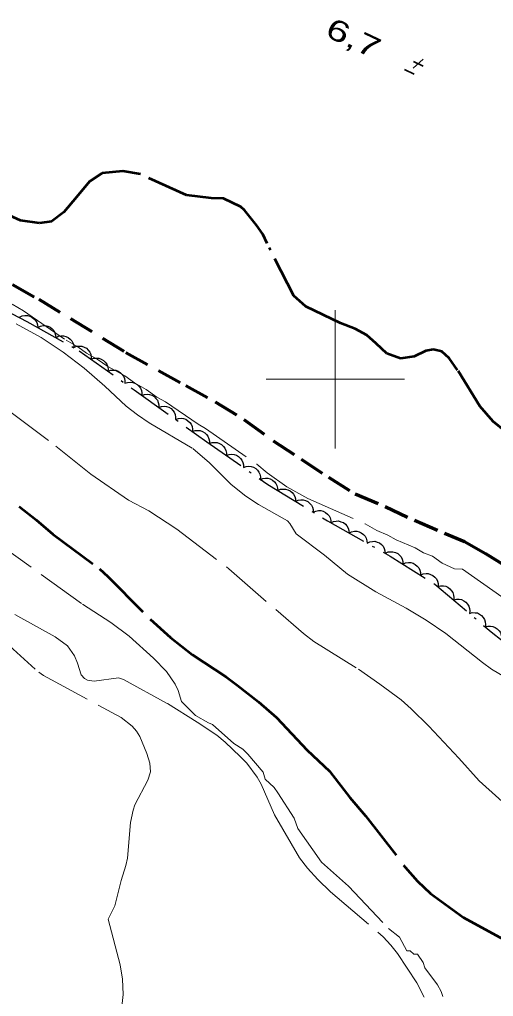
# Model space of a CAD drawing. Extents: x 355726 to 357533, y 5103782 to 5105258.
# Drawn here: x 356377.2 to 356411.4, y 5104355.4 to 5104426 of the extents above; entities that cross this region are included whole.
import ezdxf
from ezdxf.enums import TextEntityAlignment as Align

# ---------------------------------------------------------------- set-up
doc = ezdxf.new("R2010")
doc.units = 0
doc.header["$LTSCALE"] = 0.6
for name, pattern in [('DASH_DOUBLE_DOT', [9.2, 5, -1.2, 0.3, -1.2, 0.3, -1.2]), ('DOT_DASHED', [7.7, 5, -1.2, 0.3, -1.2]), ('LONG_DASHED', [7.5, 6, -1.5]), ('MEDIUM_DASHED', [4.5, 3, -1.5])]:
    doc.linetypes.add(name, pattern=pattern)
for name, color, linetype, lineweight in [('1', 7, 'LONG_DASHED', 53), ('2', 7, 'LONG_DASHED', 13), ('3', 7, 'Continuous', 140), ('4', 7, 'DASH_DOUBLE_DOT', 53), ('44', 7, 'Continuous', 25), ('61', 7, 'Continuous', 13), ('7', 7, 'MEDIUM_DASHED', 70)]:
    doc.layers.add(name, color=color, linetype=linetype, lineweight=lineweight)

msp = doc.modelspace()

# ---------------------------------------------------------------- linework, layer by layer
at = {"layer": '1'}
msp.add_lwpolyline([(356377.13, 5104390.8), (356378.36, 5104389.84), (356379.57, 5104388.8), (356382.95, 5104386.29), (356383.56, 5104385.74), (356386.6, 5104382.66), (356388.08, 5104381.32), (356389.68, 5104380.07), (356392.12, 5104378.47), (356392.91, 5104377.88), (356394.45, 5104376.68), (356395.75, 5104375.54), (356397.97, 5104373.19), (356399.57, 5104371.66), (356401.04, 5104369.76), (356402.18, 5104368.43), (356405.06, 5104364.72), (356405.94, 5104363.71), (356406.88, 5104362.82), (356409.26, 5104361.09), (356412.39, 5104359.38)], dxfattribs=at)
at = {"layer": '2'}
for points in [[(356362.95, 5104407.05), (356368.1, 5104403.34), (356373.75, 5104399.82), (356376.37, 5104397.74), (356379.79, 5104395.17), (356382.33, 5104393.13), (356385.04, 5104391.26), (356386.51, 5104390.48), (356388.54, 5104389.15), (356392.29, 5104386.3), (356397.69, 5104381.62), (356398.45, 5104381.05), (356401.68, 5104379.03), (356403.23, 5104377.96), (356404.75, 5104376.82), (356405.49, 5104376.18), (356406.75, 5104374.93), (356408.93, 5104372.61), (356410.4, 5104370.97), (356416.1, 5104365.82)], [(356376.63, 5104405.41), (356377.46, 5104404.94), (356380.54, 5104402.81), (356381.38, 5104402.34), (356382.01, 5104401.88), (356382.77, 5104401.45), (356383.56, 5104400.91)], [(356376.91, 5104403.99), (356378.74, 5104403.01), (356380.31, 5104401.95), (356381.84, 5104400.8), (356383.34, 5104399.5), (356384.87, 5104398.05), (356385.69, 5104397.42), (356386.54, 5104396.84), (356389.69, 5104394.98), (356390.9, 5104393.96), (356392.47, 5104392.38), (356393.52, 5104391.55), (356394.45, 5104390.93), (356396.53, 5104389.76), (356396.71, 5104389.57), (356397.16, 5104388.82), (356399.22, 5104387.28), (356400.88, 5104385.91), (356402.93, 5104384.63), (356405.13, 5104383.46), (356406.57, 5104382.58), (356407.98, 5104381.61), (356410.63, 5104379.51), (356411.29, 5104379.04), (356413.4, 5104377.78)], [(356383.56, 5104400.91), (356384.77, 5104400.23), (356385.48, 5104399.73), (356386.31, 5104399.26), (356387.1, 5104398.71), (356387.71, 5104398.37), (356390.08, 5104396.74), (356390.61, 5104396.44), (356394.33, 5104393.85), (356395.07, 5104393.23), (356396.5, 5104392.23), (356398.01, 5104391.38), (356402.16, 5104389.54), (356402.99, 5104389.07), (356403.79, 5104388.72), (356404.39, 5104388.38), (356405.77, 5104387.81), (356406.37, 5104387.46), (356407.02, 5104387.2), (356407.73, 5104386.7), (356408.61, 5104386.3), (356409.19, 5104386.27), (356412.04, 5104384.27)], [(356375.08, 5104388.51), (356381.72, 5104383.73), (356383.77, 5104382.41), (356385.1, 5104381.42), (356386.86, 5104379.84), (356387.8, 5104378.88), (356388.43, 5104377.95), (356388.64, 5104377.49), (356388.88, 5104376.7), (356389.9, 5104375.69), (356390.83, 5104375.15), (356391.12, 5104375.05), (356392.66, 5104373.67), (356393.31, 5104373.26), (356393.67, 5104372.9), (356394.79, 5104371.59), (356394.93, 5104371.09), (356395.58, 5104370.48), (356395.84, 5104370.11), (356397.02, 5104368.26), (356397.29, 5104367.53), (356398.99, 5104365.08), (356400.96, 5104363.36), (356403.84, 5104360.29), (356404.63, 5104359.67), (356405.16, 5104358.69), (356405.42, 5104358.69), (356405.68, 5104358.44), (356405.94, 5104358.44)], [(356376.82, 5104382.99), (356379.74, 5104381.38), (356380.64, 5104380.72), (356381.13, 5104380.01), (356381.35, 5104379.47), (356381.61, 5104378.63), (356381.86, 5104378.36), (356382.08, 5104378.24), (356382.55, 5104378.17), (356384.31, 5104378.42), (356384.68, 5104378.3), (356387.87, 5104376.55), (356390.01, 5104375.22), (356391.43, 5104374.26), (356392.04, 5104373.76), (356393.13, 5104372.72), (356393.59, 5104372.24), (356394.34, 5104371.24), (356394.64, 5104370.72), (356395.6, 5104368.51), (356397.41, 5104365.41), (356397.98, 5104364.65), (356398.73, 5104363.83), (356399.66, 5104362.94), (356403.46, 5104359.7)], [(356375.62, 5104381.44), (356378.56, 5104378.82), (356378.89, 5104378.59), (356384.51, 5104375.54), (356385.31, 5104374.93), (356385.62, 5104374.57), (356385.87, 5104374.18), (356386.37, 5104372.95), (356386.58, 5104372.24), (356386.64, 5104371.63), (356386.45, 5104371.01), (356385.5, 5104369.23), (356385.37, 5104368.84), (356385.19, 5104367.95), (356384.98, 5104365.37), (356384.86, 5104364.84), (356384.51, 5104363.76), (356384.06, 5104361.93), (356383.58, 5104360.97), (356384.43, 5104357.67), (356384.6, 5104356.63), (356384.67, 5104355.53), (356384.43, 5104353.47)], [(356403.46, 5104359.7), (356404.02, 5104359.09), (356404.5, 5104358.48), (356405.9, 5104356.36), (356406.43, 5104355.34)], [(356405.94, 5104358.44), (356406.34, 5104357.83), (356406.47, 5104357.46), (356407.38, 5104356.23), (356407.65, 5104355.74), (356407.78, 5104355.37)]]:
    msp.add_lwpolyline(points, dxfattribs=at)
at = {"layer": '3', "lineweight": 35}
for p, q in [((356406.35, 5104423.12), (356405.64, 5104422.48)), ((356405.65, 5104422.95), (356406.35, 5104422.62)), ((356404.99, 5104422.38), (356405.71, 5104422.04))]:
    msp.add_line(p, q, dxfattribs=at)
at = {"layer": '4'}
msp.add_lwpolyline([(356412.31, 5104396.23), (356411.41, 5104396.93), (356410.46, 5104398.06), (356408.84, 5104400.66), (356408.22, 5104401.51), (356407.7, 5104402), (356407.09, 5104402.15), (356406.54, 5104402.06), (356405.7, 5104401.64), (356404.72, 5104401.49), (356403.73, 5104401.86), (356402.95, 5104402.59), (356402.28, 5104403.17), (356401.44, 5104403.64), (356400.37, 5104404.04), (356397.87, 5104405.25), (356397.01, 5104406.03), (356395.06, 5104409.81), (356394.75, 5104410.49), (356394.31, 5104411.13), (356393.43, 5104412.22), (356393.17, 5104412.46), (356391.92, 5104413.07), (356391.02, 5104413.08), (356389.25, 5104413.29), (356385.91, 5104414.81), (356384.64, 5104415.03), (356383.15, 5104414.88), (356382.23, 5104414.3), (356381.28, 5104413.15), (356380.37, 5104412.08), (356379.48, 5104411.39), (356378.62, 5104411.28), (356377.23, 5104411.46), (356375.4, 5104412.29)], dxfattribs=at)
at = {"layer": '44', "linetype": 'DOT_DASHED'}
msp.add_lwpolyline([(356337.38, 5104422.65), (356344.89, 5104419.02), (356351.48, 5104415.89), (356356.51, 5104413.86), (356359.85, 5104412.37), (356363.96, 5104410.85), (356367.24, 5104409.6), (356377.7, 5104404.18), (356381.48, 5104402.05), (356385.46, 5104399.22), (356390.71, 5104395.47), (356395.13, 5104392.38), (356399.43, 5104389.76), (356403.96, 5104387.21), (356407.2, 5104385.19), (356411.38, 5104381.65), (356413.99, 5104379.58)], dxfattribs=at)
at = {"layer": '44'}
for points in [[(356377.17, 5104404.48), (356377.36, 5104404.57), (356377.56, 5104404.6), (356377.73, 5104404.61), (356377.9, 5104404.56), (356378.06, 5104404.49), (356378.21, 5104404.37), (356378.33, 5104404.25), (356378.41, 5104404.1), (356378.47, 5104403.92), (356378.48, 5104403.74)], [(356378.48, 5104403.74), (356378.67, 5104403.83), (356378.87, 5104403.87), (356379.03, 5104403.87), (356379.2, 5104403.83), (356379.37, 5104403.75), (356379.52, 5104403.63), (356379.64, 5104403.52), (356379.72, 5104403.36), (356379.77, 5104403.18), (356379.79, 5104403)], [(356379.79, 5104403), (356379.97, 5104403.1), (356380.18, 5104403.13), (356380.34, 5104403.14), (356380.51, 5104403.09), (356380.68, 5104403.02), (356380.83, 5104402.9), (356380.94, 5104402.78), (356381.02, 5104402.62), (356381.08, 5104402.45), (356381.09, 5104402.27)], [(356381.12, 5104402.31), (356381.32, 5104402.38), (356381.52, 5104402.39), (356381.68, 5104402.38), (356381.85, 5104402.32), (356382.01, 5104402.23), (356382.14, 5104402.09), (356382.24, 5104401.96), (356382.31, 5104401.8), (356382.35, 5104401.62), (356382.34, 5104401.44)], [(356382.34, 5104401.44), (356382.54, 5104401.51), (356382.74, 5104401.52), (356382.91, 5104401.51), (356383.07, 5104401.45), (356383.23, 5104401.36), (356383.36, 5104401.22), (356383.47, 5104401.09), (356383.53, 5104400.93), (356383.57, 5104400.75), (356383.56, 5104400.57)], [(356383.56, 5104400.57), (356383.76, 5104400.64), (356383.96, 5104400.65), (356384.13, 5104400.64), (356384.29, 5104400.58), (356384.45, 5104400.49), (356384.59, 5104400.35), (356384.69, 5104400.22), (356384.75, 5104400.06), (356384.79, 5104399.88), (356384.79, 5104399.7)], [(356384.79, 5104399.7), (356384.98, 5104399.77), (356385.19, 5104399.78), (356385.35, 5104399.77), (356385.51, 5104399.71), (356385.67, 5104399.62), (356385.81, 5104399.48), (356385.91, 5104399.36), (356385.98, 5104399.19), (356386.01, 5104399.01), (356386.01, 5104398.83)], [(356386.01, 5104398.83), (356386.2, 5104398.9), (356386.41, 5104398.91), (356386.57, 5104398.9), (356386.74, 5104398.84), (356386.9, 5104398.75), (356387.03, 5104398.61), (356387.13, 5104398.48), (356387.2, 5104398.32), (356387.23, 5104398.14), (356387.23, 5104397.96)], [(356387.23, 5104397.96), (356387.42, 5104398.03), (356387.63, 5104398.04), (356387.79, 5104398.03), (356387.96, 5104397.97), (356388.12, 5104397.87), (356388.25, 5104397.74), (356388.35, 5104397.61), (356388.42, 5104397.45), (356388.45, 5104397.26), (356388.45, 5104397.08)], [(356388.45, 5104397.08), (356388.65, 5104397.16), (356388.85, 5104397.17), (356389.01, 5104397.16), (356389.18, 5104397.1), (356389.34, 5104397), (356389.47, 5104396.87), (356389.57, 5104396.74), (356389.64, 5104396.57), (356389.67, 5104396.39), (356389.67, 5104396.21)], [(356389.67, 5104396.21), (356389.87, 5104396.29), (356390.07, 5104396.3), (356390.23, 5104396.29), (356390.4, 5104396.22), (356390.56, 5104396.13), (356390.69, 5104395.99), (356390.79, 5104395.87), (356390.86, 5104395.7), (356390.9, 5104395.52), (356390.89, 5104395.34)], [(356390.89, 5104395.34), (356391.09, 5104395.42), (356391.29, 5104395.43), (356391.45, 5104395.42), (356391.62, 5104395.36), (356391.78, 5104395.27), (356391.92, 5104395.13), (356392.02, 5104395.01), (356392.08, 5104394.84), (356392.12, 5104394.66), (356392.12, 5104394.48)], [(356392.12, 5104394.48), (356392.32, 5104394.56), (356392.52, 5104394.57), (356392.68, 5104394.56), (356392.85, 5104394.5), (356393.01, 5104394.41), (356393.15, 5104394.27), (356393.25, 5104394.15), (356393.31, 5104393.98), (356393.35, 5104393.8), (356393.35, 5104393.62)], [(356393.35, 5104393.62), (356393.55, 5104393.7), (356393.75, 5104393.71), (356393.91, 5104393.7), (356394.08, 5104393.64), (356394.24, 5104393.55), (356394.38, 5104393.42), (356394.48, 5104393.29), (356394.54, 5104393.13), (356394.58, 5104392.94), (356394.58, 5104392.76)], [(356394.56, 5104392.73), (356394.75, 5104392.82), (356394.95, 5104392.84), (356395.11, 5104392.84), (356395.28, 5104392.79), (356395.45, 5104392.71), (356395.59, 5104392.59), (356395.7, 5104392.47), (356395.78, 5104392.31), (356395.83, 5104392.13), (356395.84, 5104391.95)], [(356395.84, 5104391.95), (356396.03, 5104392.04), (356396.23, 5104392.06), (356396.39, 5104392.06), (356396.56, 5104392.01), (356396.73, 5104391.93), (356396.87, 5104391.8), (356396.98, 5104391.69), (356397.06, 5104391.53), (356397.11, 5104391.35), (356397.12, 5104391.17)], [(356397.12, 5104391.17), (356397.31, 5104391.25), (356397.51, 5104391.28), (356397.68, 5104391.28), (356397.84, 5104391.23), (356398.01, 5104391.15), (356398.15, 5104391.02), (356398.27, 5104390.9), (356398.34, 5104390.75), (356398.39, 5104390.57), (356398.4, 5104390.39)], [(356398.4, 5104390.39), (356398.59, 5104390.47), (356398.79, 5104390.5), (356398.96, 5104390.5), (356399.13, 5104390.45), (356399.29, 5104390.37), (356399.44, 5104390.24), (356399.55, 5104390.12), (356399.62, 5104389.97), (356399.67, 5104389.79), (356399.68, 5104389.61)], [(356399.69, 5104389.62), (356399.87, 5104389.71), (356400.07, 5104389.74), (356400.24, 5104389.75), (356400.41, 5104389.7), (356400.58, 5104389.63), (356400.73, 5104389.51), (356400.84, 5104389.39), (356400.92, 5104389.24), (356400.98, 5104389.06), (356400.99, 5104388.88)], [(356400.99, 5104388.88), (356401.18, 5104388.97), (356401.38, 5104389.01), (356401.55, 5104389.01), (356401.72, 5104388.97), (356401.88, 5104388.89), (356402.03, 5104388.77), (356402.15, 5104388.66), (356402.23, 5104388.5), (356402.29, 5104388.32), (356402.3, 5104388.14)], [(356402.3, 5104388.14), (356402.49, 5104388.24), (356402.69, 5104388.27), (356402.85, 5104388.28), (356403.02, 5104388.23), (356403.19, 5104388.16), (356403.34, 5104388.04), (356403.46, 5104387.92), (356403.54, 5104387.76), (356403.59, 5104387.59), (356403.61, 5104387.41)], [(356403.62, 5104387.42), (356403.81, 5104387.51), (356404.01, 5104387.53), (356404.17, 5104387.53), (356404.34, 5104387.48), (356404.51, 5104387.4), (356404.65, 5104387.27), (356404.76, 5104387.15), (356404.83, 5104386.99), (356404.88, 5104386.81), (356404.89, 5104386.63)], [(356404.89, 5104386.63), (356405.08, 5104386.72), (356405.28, 5104386.74), (356405.45, 5104386.74), (356405.62, 5104386.69), (356405.78, 5104386.6), (356405.92, 5104386.48), (356406.03, 5104386.36), (356406.11, 5104386.2), (356406.16, 5104386.02), (356406.16, 5104385.84)], [(356406.16, 5104385.84), (356406.35, 5104385.92), (356406.56, 5104385.95), (356406.72, 5104385.95), (356406.89, 5104385.89), (356407.05, 5104385.81), (356407.2, 5104385.68), (356407.31, 5104385.56), (356407.38, 5104385.4), (356407.43, 5104385.22), (356407.44, 5104385.04)], [(356407.41, 5104385.01), (356407.61, 5104385.07), (356407.82, 5104385.06), (356407.98, 5104385.04), (356408.14, 5104384.96), (356408.29, 5104384.85), (356408.41, 5104384.71), (356408.5, 5104384.57), (356408.55, 5104384.4), (356408.58, 5104384.22), (356408.56, 5104384.04)], [(356408.56, 5104384.04), (356408.76, 5104384.1), (356408.96, 5104384.09), (356409.12, 5104384.07), (356409.28, 5104383.99), (356409.43, 5104383.89), (356409.56, 5104383.74), (356409.65, 5104383.6), (356409.7, 5104383.43), (356409.72, 5104383.25), (356409.7, 5104383.07)], [(356409.7, 5104383.07), (356409.9, 5104383.13), (356410.11, 5104383.12), (356410.27, 5104383.1), (356410.43, 5104383.02), (356410.58, 5104382.92), (356410.7, 5104382.77), (356410.79, 5104382.63), (356410.84, 5104382.47), (356410.86, 5104382.28), (356410.85, 5104382.1)], [(356410.83, 5104382.09), (356411.03, 5104382.15), (356411.23, 5104382.15), (356411.4, 5104382.13), (356411.56, 5104382.06), (356411.71, 5104381.96), (356411.84, 5104381.82), (356411.94, 5104381.68), (356411.99, 5104381.52), (356412.02, 5104381.33), (356412.01, 5104381.15)]]:
    msp.add_lwpolyline(points, dxfattribs=at)
at = {"layer": '61'}
for p, q in [((356400, 5104395), (356400, 5104405)), ((356395, 5104400), (356405, 5104400))]:
    msp.add_line(p, q, dxfattribs=at)
at = {"layer": '7'}
msp.add_lwpolyline([(356360.74, 5104417.76), (356361.79, 5104417.09), (356362.57, 5104416.36), (356364.66, 5104414.74), (356366.76, 5104413.36), (356368.39, 5104412.34), (356370.65, 5104410.87), (356374.7, 5104408.15), (356376.66, 5104406.85), (356378.55, 5104405.78), (356384.85, 5104401.94), (356389.19, 5104399.55), (356391.31, 5104398.36), (356393.39, 5104397.09), (356395.51, 5104395.55), (356397.54, 5104394.21), (356399.5, 5104392.91), (356401.43, 5104391.72), (356403.6, 5104390.8), (356405.72, 5104389.8), (356407.89, 5104388.88), (356409.34, 5104388.26), (356410.85, 5104387.41), (356412.48, 5104386.39)], dxfattribs=at)

# ---------------------------------------------------------------- texts
at = {"layer": '3', "width": 1.45}
msp.add_text('    6,7', height=1.5, rotation=334.72, dxfattribs=at).set_placement((356399.535, 5104424.667), align=Align.CENTER)

doc.saveas('drawing.dxf')
